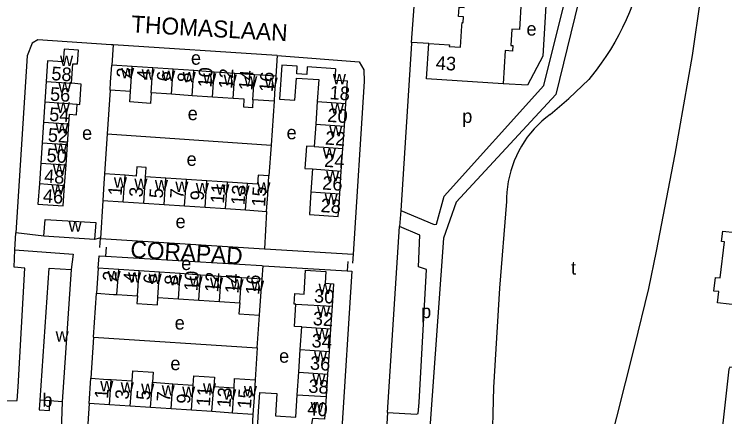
# Model space of a CAD drawing. Extents: x 161773 to 163836, y 384796 to 386521.
# Drawn here: x 162037.7 to 162246.8, y 385877.5 to 385996.1 of the extents above; entities that cross this region are included whole.
import ezdxf

# ---------------------------------------------------------------- set-up
doc = ezdxf.new("R2010")
doc.units = 0
for name, color, linetype in [('BLT_Basislijn', 7, 'Continuous'), ('BLT_Bebouwing', 7, 'Continuous'), ('BLT_Centroide', 7, 'Continuous'), ('BLT_Huisnummer', 7, 'Continuous'), ('BLT_Huisnummer_ tussenligend', 7, 'Continuous'), ('BLT_Onderverdeling_panden', 7, 'Continuous'), ('BLT_Straatnaam', 7, 'Continuous')]:
    doc.layers.add(name, color=color, linetype=linetype)

msp = doc.modelspace()

# ---------------------------------------------------------------- linework, layer by layer
at = {"layer": 'BLT_Basislijn'}
for p, q in [((162154.55, 385987.69), (162155.61, 386001.09)), ((162066.79, 385987.05), (162066.39, 385981.06)), ((162159.65, 385987.43), (162154.55, 385987.69)), ((162115.03, 385983.9), (162114.66, 385977.8)), ((162065.89, 385973.67), (162065.05, 385960.8)), ((162114.16, 385970.44), (162113.28, 385957.46)), ((162065.05, 385960.8), (162064.27, 385949.02)), ((162065.05, 385960.8), (162113.28, 385957.46)), ((162113.28, 385957.46), (162112.66, 385948.43)), ((162063.75, 385941.22), (162063.09, 385930.03)), ((162111.95, 385937.97), (162111.31, 385926.96)), ((162151.41, 385938.24), (162151.1, 385933.52)), ((162147.54, 385878.69), (162151.1, 385933.52)), ((162037.86, 385926.6), (162038.14, 385931.61)), ((162046.46, 385930.69), (162038.14, 385931.61)), ((162062.97, 385930.04), (162062.79, 385927.31)), ((162063.09, 385930.03), (162062.97, 385930.04)), ((162063.09, 385930.03), (162111.31, 385926.96)), ((162064.73, 385927.46), (162064.56, 385924.79)), ((162137.4, 385925.4), (162137.22, 385922.67)), ((162135.85, 385923.22), (162135.67, 385920.47)), ((162110.63, 385918.01), (162110.95, 385921.97)), ((162110.95, 385921.97), (162135.67, 385920.47)), ((162137.07, 385920.38), (162133.61, 385865.64)), ((162135.67, 385920.47), (162137.07, 385920.38)), ((162060.99, 385900.9), (162061.91, 385913.87)), ((162109.2, 385897.73), (162109.91, 385907.36)), ((162060.99, 385900.9), (162060.24, 385888.83)), ((162060.99, 385900.9), (162109.2, 385897.73)), ((162109.2, 385897.73), (162108.62, 385888.34)), ((162059.73, 385881.41), (162059.05, 385870.21)), ((162147.54, 385878.69), (162147.22, 385873.69)), ((162107.93, 385878.16), (162107.3, 385867.25))]:
    msp.add_line(p, q, dxfattribs=at)
for points in [[(162222.66, 386076.72), (162222.42, 386075.78), (162221.94, 386075.27), (162220.69, 386070.17), (162216.01, 386049.98), (162197.07, 385972.43), (162167.75, 385940.71), (162164.04, 385930.05), (162159.87, 385872.82), (162161.24, 385746.35)], [(162151.41, 385938.24), (162161.22, 385934.09), (162161.96, 385934.17), (162164.25, 385942.46), (162193.53, 385975.09), (162209.23, 386038.09)], [(162241.92, 386017.31), (162239.68, 386001.07), (162237.2, 385983.86), (162232.1, 385954.86), (162226.57, 385926.28)], [(162223.05, 386010.76), (162222.53, 386008.35), (162221.93, 386005.96), (162221.25, 386003.6), (162220.49, 386001.25), (162219.67, 385998.93), (162218.76, 385996.65), (162217.78, 385994.39), (162216.73, 385992.16), (162215.61, 385989.97), (162214.41, 385987.82), (162213.15, 385985.7), (162211.82, 385983.63), (162210.42, 385981.6), (162208.96, 385979.62), (162207.43, 385977.69), (162206.75, 385976.87)], [(162190.42, 386005.59), (162194.48, 386005.35), (162193.21, 385983.74), (162188.76, 385975.15), (162181.57, 385975.58)], [(162066.79, 385987.05), (162066.27, 385987.08), (162044.64, 385988.47), (162043.01, 385987.57), (162041.51, 385983.79), (162038.14, 385931.61)], [(162115.03, 385983.9), (162114.93, 385983.91), (162066.79, 385987.05)], [(162154.55, 385987.69), (162154.55, 385987.43), (162151.41, 385938.24)], [(162115.03, 385983.9), (162139.2, 385981.99), (162140.55, 385979.68), (162140.63, 385976.24), (162137.4, 385925.4)], [(162195.39, 385966.52), (162200.92, 385971.18), (162206.75, 385976.87)], [(162195.39, 385966.52), (162194.13, 385965.55), (162192.93, 385964.51), (162191.78, 385963.42), (162190.69, 385962.27), (162189.65, 385961.06), (162188.68, 385959.81), (162187.77, 385958.51), (162186.93, 385957.16), (162186.16, 385955.77), (162185.46, 385954.35), (162184.83, 385952.89), (162184.28, 385951.41), (162183.8, 385949.89), (162183.4, 385948.36), (162183.07, 385946.8), (162182.83, 385945.24), (162182.66, 385943.66), (162182.58, 385942.07), (162182.56, 385940.86)], [(162182.56, 385940.86), (162180.52, 385915.35), (162178.77, 385886.05), (162178.19, 385866.81), (162177.9, 385860.98)], [(162147.54, 385878.69), (162156.08, 385878.23), (162156.56, 385878.44), (162156.82, 385881.71), (162159, 385920.88), (162156.7, 385921.61), (162157.02, 385931), (162151.1, 385933.52)], [(162062.97, 385930.04), (162062.84, 385930.05), (162061.37, 385929.71)], [(162034.19, 385871.62), (162034.89, 385882.19), (162038.52, 385882.21), (162038.88, 385886.32), (162040.81, 385921.26), (162037.64, 385921.55), (162037.86, 385926.6)], [(162037.86, 385926.6), (162055.09, 385925.38), (162054.41, 385920.86)], [(162111.31, 385926.96), (162111.43, 385926.95), (162137.4, 385925.4)], [(162062.41, 385921.27), (162062.66, 385924.91), (162064.56, 385924.79)], [(162064.56, 385924.79), (162110.55, 385922), (162110.95, 385921.97)], [(162226.57, 385926.28), (162224.38, 385915.21), (162220.16, 385898), (162212.29, 385866.81)], [(162262.04, 385890.76), (162249.29, 385892.02), (162248.28, 385892.03), (162247.96, 385891.53), (162231.14, 385739.66)], [(162051.78, 385881.91), (162051.45, 385870.49), (162034.19, 385871.62)]]:
    msp.add_lwpolyline(points, dxfattribs=at)
at = {"layer": 'BLT_Bebouwing'}
for p, q in [((162072.42, 385980.65), (162066.39, 385981.06)), ((162078.46, 385980.24), (162072.42, 385980.65)), ((162084.49, 385979.84), (162078.46, 385980.24)), ((162090.52, 385979.43), (162084.49, 385979.84)), ((162096.56, 385979.02), (162090.52, 385979.43)), ((162102.59, 385978.61), (162096.56, 385979.02)), ((162108.42, 385978.22), (162102.59, 385978.61)), ((162114.66, 385977.8), (162108.42, 385978.22)), ((162047.13, 385976.28), (162046.73, 385970.25)), ((162071.93, 385973.26), (162065.89, 385973.67)), ((162084, 385972.46), (162077.96, 385972.86)), ((162090.03, 385972.05), (162084, 385972.46)), ((162096.06, 385971.65), (162090.03, 385972.05)), ((162102.1, 385971.24), (162096.06, 385971.65)), ((162114.16, 385970.44), (162107.94, 385970.85)), ((162126.86, 385970.34), (162126.4, 385963.69)), ((162046.73, 385970.25), (162046.32, 385964.22)), ((162134.85, 385963.1), (162135.32, 385969.75)), ((162046.32, 385964.22), (162045.91, 385958.2)), ((162053.34, 385957.7), (162053.75, 385963.72)), ((162126.4, 385963.69), (162125.93, 385957.04)), ((162134.39, 385956.45), (162134.85, 385963.1)), ((162045.91, 385958.2), (162045.51, 385952.17)), ((162052.94, 385951.67), (162053.34, 385957.7)), ((162133.93, 385949.8), (162134.39, 385956.45)), ((162045.51, 385952.17), (162045.1, 385946.14)), ((162052.53, 385945.64), (162052.94, 385951.67)), ((162125.48, 385950.48), (162125.01, 385943.74)), ((162133.47, 385943.15), (162133.93, 385949.8)), ((162070.3, 385948.61), (162064.27, 385949.02)), ((162082.35, 385947.8), (162076.33, 385948.2)), ((162088.38, 385947.39), (162082.35, 385947.8)), ((162094.4, 385946.98), (162088.38, 385947.39)), ((162100.43, 385946.58), (162094.4, 385946.98)), ((162106.3, 385946.18), (162100.43, 385946.58)), ((162063.75, 385941.22), (162069.77, 385940.81)), ((162069.77, 385940.81), (162075.8, 385940.41)), ((162075.8, 385940.41), (162081.83, 385940)), ((162081.83, 385940), (162087.85, 385939.59)), ((162087.85, 385939.59), (162093.88, 385939.19)), ((162093.88, 385939.19), (162099.9, 385938.78)), ((162099.9, 385938.78), (162105.78, 385938.38)), ((162105.78, 385938.38), (162111.95, 385937.97)), ((162061.37, 385929.71), (162046.46, 385930.69)), ((162054.41, 385920.86), (162051.78, 385881.91)), ((162062.41, 385921.27), (162061.91, 385913.87)), ((162068.44, 385920.86), (162062.41, 385921.27)), ((162074.46, 385920.45), (162068.44, 385920.86)), ((162080.49, 385920.05), (162074.46, 385920.45)), ((162086.52, 385919.64), (162080.49, 385920.05)), ((162092.55, 385919.23), (162086.52, 385919.64)), ((162098.58, 385918.83), (162092.55, 385919.23)), ((162104.61, 385918.42), (162098.58, 385918.83)), ((162110.63, 385918.01), (162104.61, 385918.42)), ((162067.94, 385913.46), (162073.97, 385913.06)), ((162079.99, 385912.65), (162086.02, 385912.24)), ((162086.02, 385912.24), (162092.05, 385911.84)), ((162092.05, 385911.84), (162098.08, 385911.43)), ((162098.08, 385911.43), (162104.11, 385911.02)), ((162131.24, 385910.01), (162130.79, 385903.35)), ((162121.88, 385897.27), (162122.33, 385903.92)), ((162130.79, 385903.35), (162130.35, 385896.7)), ((162121.43, 385890.61), (162121.88, 385897.27)), ((162130.35, 385896.7), (162129.9, 385890.05)), ((162059.73, 385881.41), (162060.24, 385888.83)), ((162120.99, 385883.96), (162121.43, 385890.61)), ((162129.9, 385890.05), (162129.46, 385883.39)), ((162066.26, 385888.42), (162072.36, 385888.01)), ((162078.35, 385887.61), (162084.34, 385887.2)), ((162084.34, 385887.2), (162090.36, 385886.8)), ((162096.39, 385886.39), (162102.42, 385885.98)), ((162051.78, 385881.91), (162048.22, 385882.15)), ((162065.76, 385881), (162059.73, 385881.41)), ((162071.79, 385880.6), (162065.76, 385881)), ((162077.81, 385880.19), (162071.79, 385880.6)), ((162083.84, 385879.78), (162077.81, 385880.19)), ((162089.86, 385879.38), (162083.84, 385879.78)), ((162095.89, 385878.97), (162089.86, 385879.38)), ((162101.92, 385878.56), (162095.89, 385878.97)), ((162107.93, 385878.16), (162101.92, 385878.56))]:
    msp.add_line(p, q, dxfattribs=at)
for points in [[(162169.43, 385992.59), (162169.49, 385993.64), (162169.83, 385993.61), (162169.93, 385995.3), (162168.44, 385995.4), (162168.61, 385998.09), (162170.1, 385997.99), (162170.22, 386000)], [(162186.91, 386000), (162186.37, 385991.51), (162184.08, 385991.66)], [(162159.65, 385987.43), (162165.73, 385987.05), (162165.7, 385986.58), (162169.03, 385986.37), (162169.43, 385992.59)], [(162184.08, 385991.66), (162183.78, 385986.89), (162184.45, 385986.84), (162184.35, 385985.2), (162182.19, 385985.34), (162181.57, 385975.58)], [(162181.57, 385975.58), (162158.99, 385977.01), (162159.65, 385987.43)], [(162054.95, 385981.49), (162056.3, 385981.4), (162056.58, 385985.51), (162052.39, 385985.79), (162052.13, 385982), (162047.54, 385982.31), (162047.13, 385976.28)], [(162054.56, 385975.78), (162054.95, 385981.49)], [(162065.89, 385973.67), (162066.06, 385976.07), (162066.39, 385981.06)], [(162132.26, 385979.96), (162123.92, 385980.54), (162123.76, 385978.27), (162120.82, 385978.48), (162120.97, 385980.76), (162116.4, 385981.08), (162115.73, 385971.07), (162120.3, 385970.76), (162120.73, 385977.23), (162127.29, 385976.79), (162126.86, 385970.34)], [(162132.26, 385979.96), (162132.03, 385976.66), (162135.77, 385976.4)], [(162114.66, 385977.8), (162114.32, 385972.81), (162114.16, 385970.44)], [(162056.24, 385969.54), (162057.03, 385969.48), (162057.43, 385975.45), (162054.56, 385975.78)], [(162135.32, 385969.75), (162135.77, 385976.4)], [(162077.96, 385972.86), (162077.76, 385969.8), (162071.72, 385970.21), (162071.93, 385973.26)], [(162107.94, 385970.85), (162107.78, 385968.49), (162105.23, 385968.65), (162105.39, 385971.02), (162102.1, 385971.24)], [(162053.75, 385963.72), (162053.94, 385966.59), (162056.03, 385966.45), (162056.24, 385969.54)], [(162125.93, 385957.04), (162123.73, 385957.21), (162123.25, 385950.64), (162125.48, 385950.48)], [(162076.33, 385948.2), (162076.51, 385950.87), (162073.75, 385951.06), (162073.57, 385948.39), (162070.3, 385948.61)], [(162064.27, 385949.02), (162064.08, 385946.21), (162063.75, 385941.22)], [(162112.66, 385948.43), (162109.47, 385948.65), (162109.26, 385945.98), (162106.3, 385946.18)], [(162111.95, 385937.97), (162112.29, 385942.96), (162112.66, 385948.43)], [(162045.1, 385946.14), (162044.69, 385940.11), (162052.12, 385939.61), (162052.12, 385939.61), (162052.53, 385945.64)], [(162125.01, 385943.74), (162124.55, 385937.09), (162133.01, 385936.5), (162133.47, 385943.15)], [(162046.46, 385930.69), (162046.83, 385935.6), (162061.69, 385934.66), (162061.37, 385929.71)], [(162251.54, 385910.59), (162251.5, 385910.26), (162244.63, 385911.04), (162245, 385914.34), (162243.55, 385914.51), (162244.01, 385918.53), (162245.47, 385918.36), (162246.68, 385929.01), (162245.83, 385929.1), (162246.18, 385932.17), (162249.82, 385931.75)], [(162045.34, 385882.34), (162047.96, 385921.29), (162054.41, 385920.86)], [(162120.59, 385910.61), (162120.08, 385910.64), (162120.28, 385913.75), (162122.97, 385913.57), (162123.22, 385917.23), (162123.45, 385920.65), (162129.42, 385920.25), (162129.19, 385916.83), (162131.68, 385916.66), (162131.24, 385910.01)], [(162109.91, 385907.36), (162110.3, 385913.03), (162110.63, 385918.01)], [(162061.91, 385913.87), (162066.9, 385913.53), (162067.94, 385913.46)], [(162073.97, 385913.06), (162073.82, 385910.84), (162079.84, 385910.43), (162079.99, 385912.65)], [(162104.11, 385911.02), (162103.76, 385907.78), (162109.91, 385907.36)], [(162122.33, 385903.92), (162120.15, 385904.02), (162120.59, 385910.61)], [(162072.36, 385888.01), (162072.56, 385891.01), (162078.55, 385890.6), (162078.35, 385887.61)], [(162060.24, 385888.83), (162065.22, 385888.49), (162066.26, 385888.42)], [(162090.36, 385886.8), (162090.51, 385889.57), (162096.62, 385889.12), (162096.39, 385886.39)], [(162102.42, 385885.98), (162102.48, 385888.76), (162108.62, 385888.34)], [(162108.62, 385888.34), (162108.27, 385883.14), (162107.93, 385878.16)], [(162129.46, 385883.39), (162129.02, 385876.76), (162125.49, 385876.99), (162124.76, 385872.95), (162109.28, 385873.98), (162109.62, 385878.97), (162109.99, 385884.62), (162114.98, 385884.29), (162114.54, 385877.7), (162120.54, 385877.3), (162120.99, 385883.96)], [(162045.34, 385882.34), (162045.19, 385882.35), (162045.01, 385879.52), (162048.04, 385879.34), (162048.22, 385882.15)], [(162048.22, 385882.15), (162045.34, 385882.34)]]:
    msp.add_lwpolyline(points, dxfattribs=at)
at = {"layer": 'BLT_Onderverdeling_panden'}
for p, q in [((162071.93, 385973.26), (162072.42, 385980.65)), ((162077.96, 385972.86), (162078.46, 385980.24)), ((162084, 385972.46), (162084.49, 385979.84)), ((162090.03, 385972.05), (162090.52, 385979.43)), ((162096.06, 385971.65), (162096.56, 385979.02)), ((162102.1, 385971.24), (162102.59, 385978.61)), ((162107.94, 385970.85), (162108.42, 385978.22)), ((162047.13, 385976.28), (162054.56, 385975.78)), ((162126.86, 385970.34), (162135.32, 385969.75)), ((162046.73, 385970.25), (162056.24, 385969.54)), ((162046.32, 385964.22), (162053.75, 385963.72)), ((162126.4, 385963.69), (162134.85, 385963.1)), ((162045.91, 385958.2), (162053.34, 385957.7)), ((162125.93, 385957.04), (162134.39, 385956.45)), ((162045.51, 385952.17), (162052.94, 385951.67)), ((162125.48, 385950.48), (162133.93, 385949.8)), ((162069.77, 385940.81), (162070.3, 385948.61)), ((162075.8, 385940.41), (162076.33, 385948.2)), ((162081.83, 385940), (162082.35, 385947.8)), ((162087.85, 385939.59), (162088.38, 385947.39)), ((162045.1, 385946.14), (162052.53, 385945.64)), ((162093.88, 385939.19), (162094.4, 385946.98)), ((162099.9, 385938.78), (162100.43, 385946.58)), ((162105.78, 385938.38), (162106.3, 385946.18)), ((162125.01, 385943.74), (162133.47, 385943.15)), ((162067.94, 385913.46), (162068.44, 385920.86)), ((162073.97, 385913.06), (162074.46, 385920.45)), ((162079.99, 385912.65), (162080.49, 385920.05)), ((162086.02, 385912.24), (162086.52, 385919.64)), ((162092.05, 385911.84), (162092.55, 385919.23)), ((162098.08, 385911.43), (162098.58, 385918.83)), ((162104.11, 385911.02), (162104.61, 385918.42)), ((162120.59, 385910.61), (162131.24, 385910.01)), ((162122.33, 385903.92), (162130.79, 385903.35)), ((162121.88, 385897.27), (162130.35, 385896.7)), ((162121.43, 385890.61), (162129.9, 385890.05)), ((162065.76, 385881), (162066.26, 385888.42)), ((162071.79, 385880.6), (162072.36, 385888.01)), ((162077.81, 385880.19), (162078.35, 385887.61)), ((162083.84, 385879.78), (162084.34, 385887.2)), ((162089.86, 385879.38), (162090.36, 385886.8)), ((162095.89, 385878.97), (162096.39, 385886.39)), ((162101.92, 385878.56), (162102.42, 385885.98)), ((162120.99, 385883.96), (162129.46, 385883.39))]:
    msp.add_line(p, q, dxfattribs=at)

# ---------------------------------------------------------------- texts
at = {"layer": 'BLT_Centroide'}
for s, p in [('e', (162188.43, 385989.76)), ('w', (162051.17, 385980.78)), ('e', (162089.7, 385981.18)), ('w', (162069.16, 385977.16)), ('w', (162075.19, 385976.75)), ('w', (162081.22, 385976.34)), ('w', (162087.27, 385975.95)), ('w', (162093.3, 385975.55)), ('w', (162099.33, 385975.14)), ('w', (162105.36, 385974.73)), ('w', (162111.39, 385974.33)), ('w', (162131.45, 385975.41)), ('w', (162050.64, 385973)), ('w', (162050.23, 385967)), ('w', (162130.86, 385966.72)), ('e', (162088.74, 385964.85)), ('p', (162169.52, 385964.03)), ('w', (162049.83, 385960.97)), ('e', (162057.66, 385959.08)), ('e', (162117.84, 385959.21)), ('w', (162130.39, 385960.06)), ('w', (162049.42, 385954.94)), ('w', (162128.52, 385953.53)), ('e', (162088.42, 385951.39)), ('w', (162049.02, 385948.91)), ('w', (162129.47, 385946.78)), ('w', (162067.02, 385944.92)), ('w', (162073.05, 385944.52)), ('w', (162048.61, 385942.88)), ('w', (162079.08, 385944.11)), ('w', (162085.09, 385943.7)), ('w', (162091.12, 385943.3)), ('w', (162097.16, 385942.89)), ('w', (162103.09, 385942.48)), ('w', (162109.22, 385943.41)), ('w', (162129.02, 385940.12)), ('w', (162053.7, 385931.98)), ('e', (162085.17, 385933.04)), ('e', (162086.83, 385920.69)), ('t', (162201.55, 385919.33)), ('w', (162065.17, 385917.38)), ('w', (162071.2, 385916.97)), ('w', (162077.23, 385916.56)), ('w', (162083.25, 385916.16)), ('w', (162089.28, 385915.75)), ('w', (162095.31, 385915.34)), ('w', (162101.34, 385914.92)), ('w', (162107.38, 385914.52)), ('w', (162127.23, 385913.62)), ('w', (162126.78, 385906.97)), ('p', (162157.41, 385906.53)), ('e', (162084.92, 385903.15)), ('w', (162126.34, 385900.31)), ('w', (162049.88, 385899.59)), ('e', (162115.63, 385893.39)), ('w', (162125.89, 385893.66)), ('e', (162083.64, 385891.2)), ('w', (162125.45, 385887)), ('w', (162063, 385884.92)), ('w', (162069.03, 385884.52)), ('w', (162075.05, 385884.11)), ('w', (162081.08, 385883.7)), ('w', (162093.23, 385884.27)), ('b', (162045.98, 385880.4)), ('w', (162087.09, 385883.3)), ('w', (162099.16, 385882.48)), ('w', (162105.27, 385883.45)), ('w', (162124.9, 385878.78))]:
    msp.add_text(s, height=4, dxfattribs=at).set_placement(p)
at = {"layer": 'BLT_Huisnummer'}
for s, rotation, p in [('43', 356.381, (162161.65, 385979.8)), ('58', 356.1414, (162048.53, 385976.66)), ('2', 86.1731, (162071.75, 385977.22)), ('6', 86.1766, (162083.6, 385976.18)), ('10', 86.172, (162095.71, 385974.35)), ('16', 86.1463, (162113.75, 385973.05)), ('18', 356.0299, (162130.4, 385971.04)), ('54', 356.1409, (162047.89, 385964.65)), ('50', 356.1404, (162047.12, 385952.59)), ('24', 356.0304, (162128.83, 385951.12)), ('1', 86.1401, (162069.3, 385942.51)), ('46', 356.1424, (162046.05, 385940.6)), ('5', 86.1391, (162081.41, 385941.72)), ('9', 86.1386, (162093.46, 385941.07)), ('15', 86.1356, (162111.51, 385939.26)), ('28', 356.0255, (162127.76, 385937.79)), ('2', 86.1402, (162067.68, 385917.32)), ('10', 86.1381, (162091.62, 385914.39)), ('6', 86.1391, (162079.65, 385916.5)), ('16', 86.1348, (162109.76, 385913.3)), ('30', 356.168, (162125.82, 385911.17)), ('34', 356.1684, (162125.12, 385897.96)), ('1', 86.1378, (162065.31, 385882.67)), ('5', 86.1367, (162077.58, 385882.27)), ('15', 86.1356, (162107.35, 385879.74)), ('9', 86.1362, (162089.43, 385881.18)), ('40', 356.1773, (162123.86, 385877.94))]:
    msp.add_text(s, height=4, rotation=rotation, dxfattribs=at).set_placement(p)
at = {"layer": 'BLT_Huisnummer_ tussenligend'}
for s, rotation, p in [('4', 86.1731, (162077.72, 385976.61)), ('8', 86.1766, (162089.69, 385975.84)), ('12', 86.172, (162101.8, 385974.01)), ('14', 86.172, (162107.76, 385973.52)), ('56', 356.1409, (162048.13, 385970.62)), ('20', 356.0299, (162129.75, 385964.38)), ('52', 356.1404, (162047.5, 385958.56)), ('22', 356.0304, (162129.09, 385957.68)), ('48', 356.1424, (162046.42, 385946.45)), ('26', 356.0304, (162128.24, 385944.43)), ('11', 86.1386, (162099.41, 385940.17)), ('13', 86.1386, (162105.47, 385939.72)), ('3', 86.1401, (162075.47, 385942.06)), ('7', 86.1391, (162087.49, 385941.58)), ('4', 86.1402, (162073.77, 385916.95)), ('8', 86.1391, (162085.86, 385916.15)), ('12', 86.1381, (162097.71, 385914.05)), ('14', 86.1381, (162103.68, 385913.67)), ('32', 356.168, (162125.48, 385904.49)), ('36', 356.1684, (162124.64, 385891.39)), ('38', 356.1684, (162124.17, 385884.58)), ('3', 86.1378, (162071.37, 385882.46)), ('7', 86.1367, (162083.55, 385881.78)), ('11', 86.1362, (162095.26, 385880.4)), ('13', 86.1362, (162101.32, 385880.07))]:
    msp.add_text(s, height=4, rotation=rotation, dxfattribs=at).set_placement(p)
at = {"layer": 'BLT_Straatnaam'}
for s, rotation, p in [('THOMASLAAN', 356.7172, (162072.01, 385990.72)), ('CORAPAD', 356.3692, (162071.76, 385924.38))]:
    msp.add_text(s, height=5, rotation=rotation, dxfattribs=at).set_placement(p)

doc.saveas('drawing.dxf')
